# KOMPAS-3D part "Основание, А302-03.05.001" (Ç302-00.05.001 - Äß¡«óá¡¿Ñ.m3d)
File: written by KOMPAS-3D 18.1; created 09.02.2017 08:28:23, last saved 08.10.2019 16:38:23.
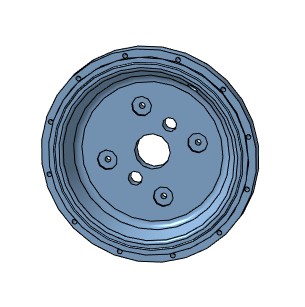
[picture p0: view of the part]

Document properties: Автор: Милов; Организация: Милов; Полное имя файла: D:\Мембранные насосы\Мембранный электропривод\А302-00.00.000 - ASTRA-302 (МЭ200)\3Д\А302-00.05.001 - Основание.m3d

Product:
- Part/product: Основание  | designation А302-03.05.001
    Материал: Полипропилен  ГОСТ 26996-86 (density 900 kg/m3)
    Масса: 1.33086
    Раздел спецификации: Детали
    Форматы листов документа: A3
- Part/product: Основание  | designation А302-00.05.001
    Материал: Полипропилен  ГОСТ 26996-86 (density 900 kg/m3)
    Масса: 1.33086
    Раздел спецификации: Детали
    Форматы листов документа: A3
    source file: \\192.168.87.28\Konstructor_doc\Мембранные насосы\Мембранный электропривод\А302-00.00.000 - ASTRA-302 (МЭ200)\Чертежи\А302-00.05.001 - Основание.cdw
- Part/product: Основание  | designation А302-04.05.001
    Материал: Полипропилен  ГОСТ 26996-86 (density 900 kg/m3)
    Масса: 1.33492
    Раздел спецификации: Детали
    Форматы листов документа: A3
    source file: ..\Чертежи ПВХ\А302-02.05.001 - Основание.cdw, ..\Чертежи Полипропилен\А302-03.05.001 - Основание.cdw
- Part/product: Основание  | designation А302-05.05.001
    Материал: Полипропилен  ГОСТ 26996-86 (density 900 kg/m3)
    Масса: 1.33492
    Раздел спецификации: Детали
    Форматы листов документа: A3

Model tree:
1. Эскиз:24
2. Операция вращения:2
     Угол 1 = 360
3. Эскиз:25  (with: Операция вращения:2)
4. Отверстие:1  (with: Операция вращения:2)
     Глубина выреза = 40; Диаметр отверстия = 8.5; Угол конуса торца = 118; Координата X = 45.9619; Координата Y = 45.9619; Диаметр цековки = 28; Глубина цековки = 4
5. Массив по концентрической сетке:1  (with: Отверстие:1, Эскиз:25)  (4 pattern instances)
     Шаг 2 = 360
6. Эскиз:26  (with: Операция вращения:2)
7. Вырезать элемент выдавливания:1
     Расстояние 1 = 40.5
8. Массив по концентрической сетке:2  (with: Вырезать элемент выдавливания:1, Эскиз:26)  (12 pattern instances)
     Шаг 2 = 360
9. Фаска:1
     Угол = 45; Длина 1 = 0.5; Длина 2 = 0.5
10. Скругление:1  (with: Операция вращения:2)
     Радиус = 12
11. Касательная плоскость:1  (with: Операция вращения:2)
12. Эскиз:27
13. Вырезать элемент выдавливания:2
     Расстояние 1 = 72.4422
14. Эскиз:28  (with: Операция вращения:2, Скругление:1)
15. Отверстие:2  (with: Операция вращения:2)
     Глубина выреза = 40; Диаметр отверстия = 8.5; Угол конуса торца = 118; Координата Y = -80; Диаметр цековки = 28; Глубина цековки = 4
16. Зеркальный массив:1
17. Экземпляр ( 1 )
18. Экземпляр ( 2 )  (with: Отверстие:2)
19. Эскиз:29  (with: Операция вращения:2, Отверстие:1, Скругление:1)
20. Вырезать элемент выдавливания:3
     Расстояние 1 = 16.5
21. Массив по концентрической сетке:3  (with: Вырезать элемент выдавливания:3, Эскиз:29)  (3 pattern instances)
     Шаг 2 = 180
22. Эскиз:30  (with: Операция вращения:2, Скругление:1)
23. Вырезать элемент выдавливания:4  (labels: Полипропилен  ГОСТ 26996-86)
     Толщина стенки 1 = 0.1; Расстояние 1 = 16.5
24. Эскиз:32  (with: Операция вращения:2, Вырезать элемент выдавливания:4)
25. Элемент выдавливания:1
     Расстояние 2 = 2
26. Эскиз:33  (with: Операция вращения:2)
27. Элемент выдавливания:2
     Толщина стенки 1 = 2; Расстояние 1 = 1
28. Скругление:2  (with: Элемент выдавливания:2)  (labels: Полипропилен  ГОСТ 26996-86)
     Радиус = 1

Expressions: 250/2-3; 19.5+5.5+3
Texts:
  Линейный размер с обрывом

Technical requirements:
  Gost Type A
